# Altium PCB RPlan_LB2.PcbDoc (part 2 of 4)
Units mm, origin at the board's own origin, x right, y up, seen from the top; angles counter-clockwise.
Board outline 38.2 x 43.28 mm, 2 copper layers (Top Layer, Bottom Layer); 36 components, 100 nets, 269 pads, 31 vias.
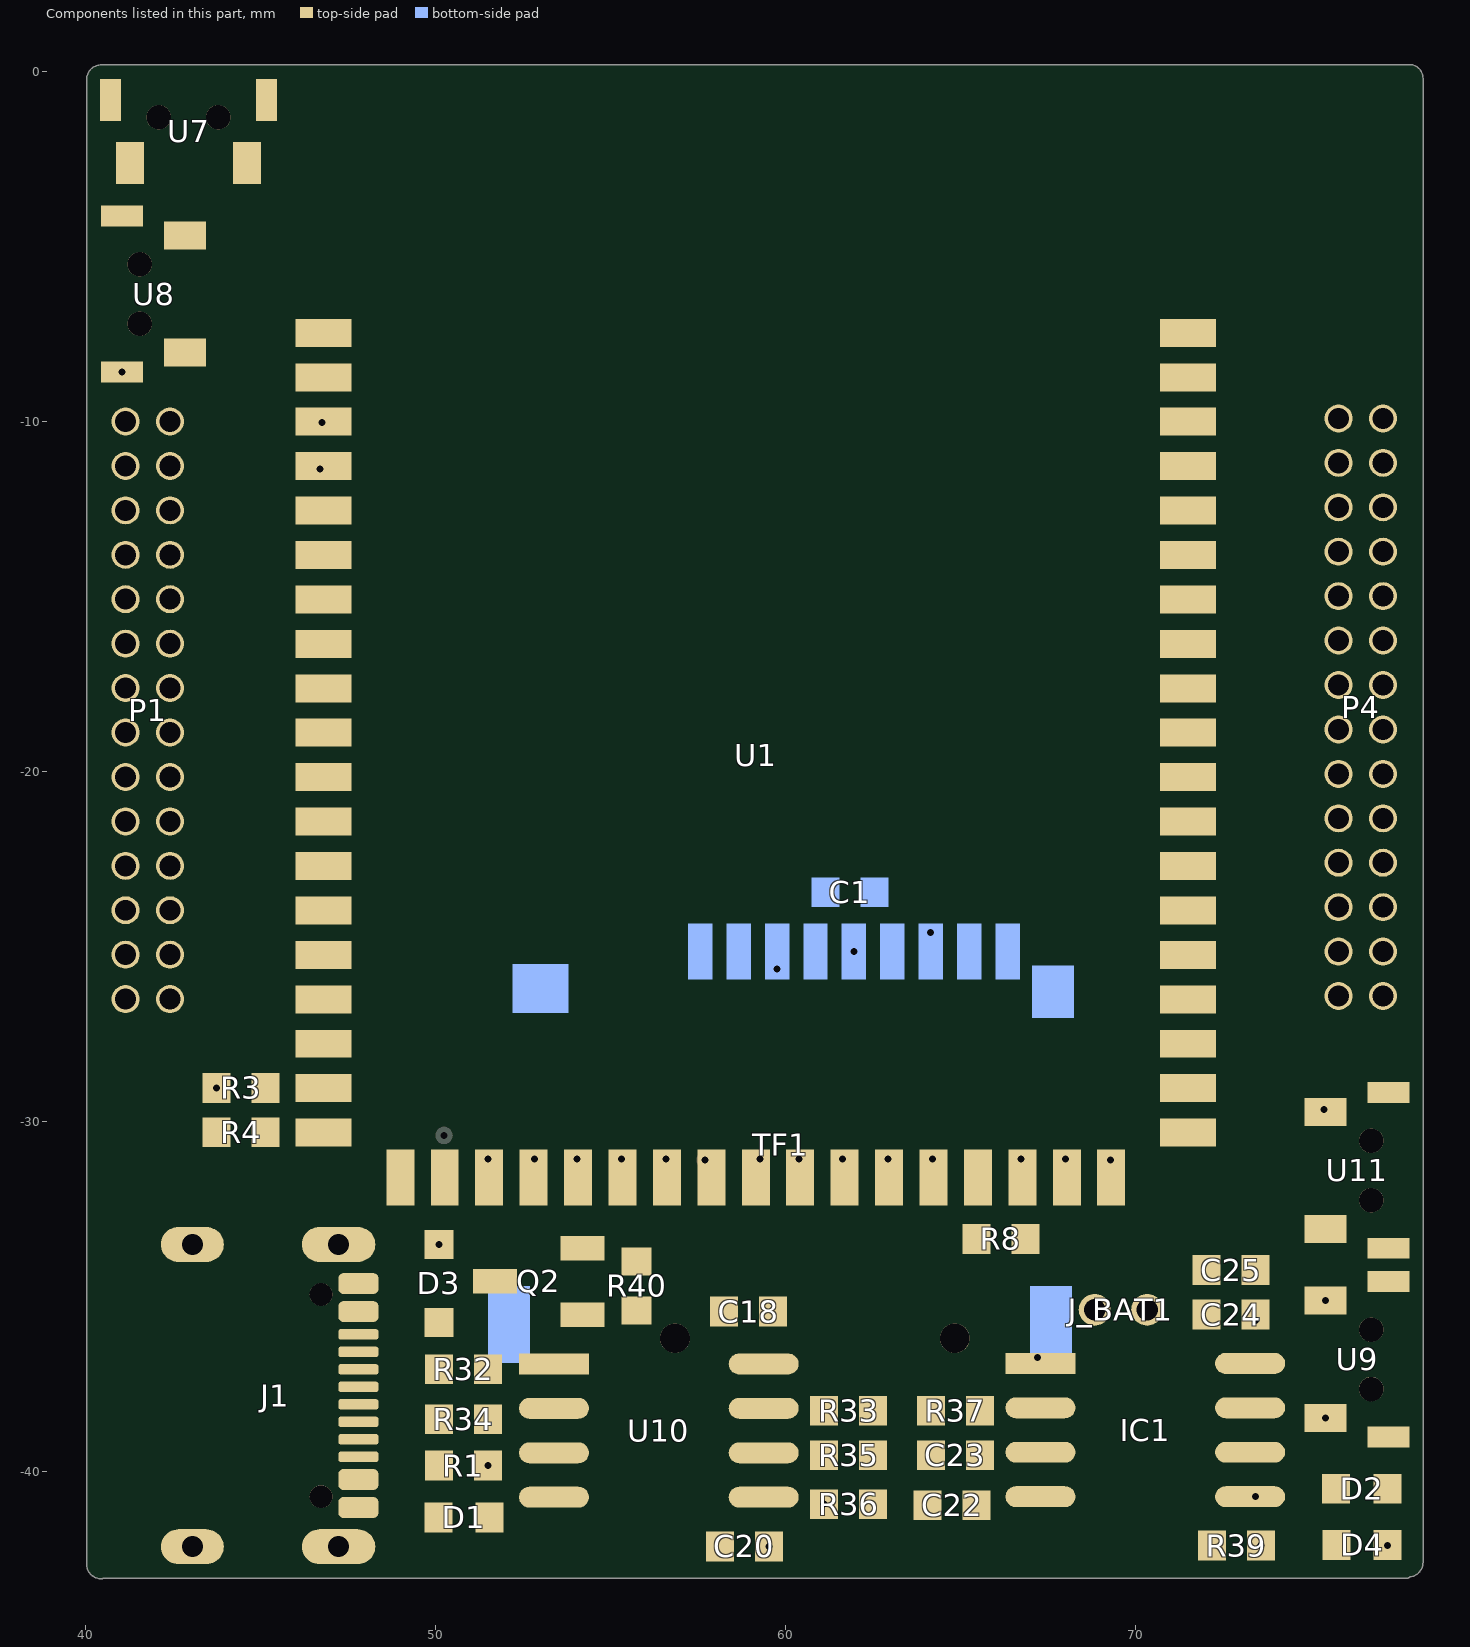
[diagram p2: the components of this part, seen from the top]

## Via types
v1: diameter 0.5, hole 0.3, Top Layer to Bottom Layer, 28 vias
v2: diameter 0.4, hole 0.2, Top Layer to Bottom Layer, 3 vias

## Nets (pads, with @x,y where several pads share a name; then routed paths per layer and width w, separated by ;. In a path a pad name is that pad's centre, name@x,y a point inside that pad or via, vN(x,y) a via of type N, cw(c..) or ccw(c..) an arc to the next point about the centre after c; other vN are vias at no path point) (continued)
copper on no net: (continued)
  Bottom Layer w0.025: 52.839,-22.09 53.525,-22.09 ; 52.839,-22.065 53.525,-22.065 ; 52.839,-22.04 53.525,-22.04 ; 52.839,-22.014 53.525,-22.014 ; 52.839,-21.989 53.525,-21.989 ; 52.839,-21.963 53.525,-21.963 ; 52.839,-21.938 53.525,-21.938 ; 52.839,-21.913 53.525,-21.913 ; 52.839,-21.887 53.525,-21.887 ; 52.839,-21.862 53.525,-21.862 ; 52.839,-21.836 53.525,-21.836 ; 52.839,-21.811 53.525,-21.811 ; 52.839,-21.786 53.525,-21.786 ; 52.839,-21.76 53.525,-21.76 ; 52.839,-21.43 53.525,-21.43 ; 52.839,-21.405 53.195,-21.405 ; 52.839,-21.379 53.195,-21.379 ; 52.839,-21.354 53.195,-21.354 ; 52.839,-21.328 53.195,-21.328 ; 52.839,-21.303 53.195,-21.303 ; 52.839,-21.278 53.195,-21.278 ; 52.839,-21.252 53.195,-21.252 ; 52.839,-21.227 53.195,-21.227 ; 52.839,-21.201 53.195,-21.201 ; 52.839,-21.176 53.195,-21.176 ; 52.839,-21.151 53.195,-21.151 ; 52.839,-21.125 53.195,-21.125 ; 52.839,-21.1 53.881,-21.1 ; 52.839,-21.074 53.881,-21.074 ; 52.839,-21.049 53.881,-21.049 ; 52.839,-21.024 53.881,-21.024 ; 52.839,-20.998 53.881,-20.998 ; 52.839,-20.973 53.881,-20.973 ; 52.839,-20.947 53.881,-20.947 ; 52.839,-20.922 53.881,-20.922 ; 52.839,-20.897 53.881,-20.897 ; 52.839,-20.871 53.881,-20.871 ; 52.839,-20.846 53.881,-20.846 ; 52.839,-20.82 53.881,-20.82 ; 52.839,-20.795 53.881,-20.795 ; 52.839,-20.77 53.881,-20.77 ; 52.839,-20.109 53.881,-20.109 ; 52.839,-20.084 53.881,-20.084 ; 52.839,-20.058 53.881,-20.058 ; 52.839,-20.033 53.881,-20.033 ; 52.839,-20.008 53.881,-20.008 ; 52.839,-19.982 53.881,-19.982 ; 52.839,-19.957 53.881,-19.957 ; 52.839,-19.931 53.881,-19.931 ; 52.839,-19.906 53.881,-19.906 ; 52.839,-19.881 53.881,-19.881 ; 52.839,-19.855 53.881,-19.855 ; 52.839,-19.83 53.881,-19.83 ; 52.839,-19.804 53.881,-19.804 ; 52.839,-19.779 53.881,-19.779 ; 52.839,-19.754 53.83,-19.754 ; 52.839,-19.728 53.195,-19.728 ; 52.839,-19.703 53.195,-19.703 ; 52.839,-19.677 53.195,-19.677 ; 52.839,-19.652 53.195,-19.652 ; 52.839,-19.627 53.195,-19.627 ; 52.839,-19.601 53.195,-19.601 ; 52.839,-19.576 53.195,-19.576 ; 52.839,-19.55 53.195,-19.55 ; 52.839,-19.525 53.195,-19.525 ; 52.839,-19.5 53.195,-19.5 ; 52.839,-19.474 53.195,-19.474 ; 52.839,-19.449 53.5,-19.449 ; 52.839,-19.119 53.525,-19.119 ; 52.839,-19.093 53.525,-19.093 ; 52.839,-19.068 53.195,-19.068 ; 52.839,-19.042 53.195,-19.042 ; 52.839,-19.017 53.195,-19.017 ; 52.839,-18.992 53.195,-18.992 ; 52.839,-18.966 53.195,-18.966 ; 52.839,-18.941 53.195,-18.941 ; 52.839,-18.915 53.195,-18.915 ; 52.839,-18.89 53.195,-18.89 ; 52.839,-18.865 53.195,-18.865 ; 52.839,-18.839 53.195,-18.839 ; 52.839,-18.814 53.195,-18.814 ; 52.839,-18.788 53.195,-18.788 ; 52.839,-18.763 53.525,-18.763 ; 52.839,-18.738 53.525,-18.738 ; 52.839,-18.712 53.525,-18.712 ; 52.839,-18.687 53.525,-18.687 ; 52.839,-18.661 53.525,-18.661 ; 52.839,-18.636 53.525,-18.636 ; 52.839,-18.611 53.525,-18.611 ; 52.839,-18.585 53.525,-18.585 ; 52.839,-18.56 53.525,-18.56 ; 52.839,-18.534 53.525,-18.534 ; 52.839,-18.509 53.525,-18.509 ; 52.839,-18.484 53.525,-18.484 ; 52.839,-18.458 53.525,-18.458 ; 52.839,-18.433 54.185,-18.433 ; 52.839,-18.407 54.185,-18.407 ; 52.839,-18.382 53.195,-18.382 ; 52.839,-18.357 53.195,-18.357 ; 52.839,-18.331 53.195,-18.331 ; 52.839,-18.306 53.195,-18.306 ; 52.839,-18.28 53.195,-18.28 ; 52.839,-18.255 53.195,-18.255 ; 52.839,-18.23 53.195,-18.23 ; 52.839,-18.204 53.195,-18.204 ; 52.839,-18.179 53.195,-18.179 ; 52.839,-18.153 53.195,-18.153 ; 52.839,-18.128 53.195,-18.128 ; 52.839,-18.103 53.195,-18.103 ; 52.839,-17.772 53.881,-17.772 ; 52.839,-17.747 53.525,-17.747 ; 52.839,-17.722 53.525,-17.722 ; 52.839,-17.696 53.525,-17.696 ; 52.839,-17.671 53.525,-17.671 ; 52.839,-17.645 53.525,-17.645 ; 52.839,-17.62 53.525,-17.62 ; 52.839,-17.595 53.525,-17.595 ; 52.839,-17.569 53.525,-17.569 ; 52.839,-17.544 53.525,-17.544 ; 52.839,-17.518 53.525,-17.518 ; 52.839,-17.493 53.525,-17.493 ; 52.839,-17.468 53.525,-17.468 ; 52.839,-17.442 53.525,-17.442 ; 52.839,-17.417 53.525,-17.417 ; 52.839,-17.391 53.195,-17.391 ; 52.839,-17.366 53.195,-17.366 ; 52.839,-17.341 53.195,-17.341 ; 52.839,-17.315 53.195,-17.315 ; 52.839,-17.29 53.195,-17.29 ; 52.839,-17.264 53.195,-17.264 ; 52.839,-17.239 53.195,-17.239 ; 52.839,-17.214 53.195,-17.214 ; 52.839,-17.188 53.195,-17.188 ; 52.839,-17.163 53.195,-17.163 ; 52.839,-17.137 53.195,-17.137 ; 52.839,-17.112 53.195,-17.112 ; 52.839,-17.087 53.195,-17.087 ; 52.839,-17.061 53.195,-17.061 ; 52.839,-17.036 53.195,-17.036 ; 52.839,-17.01 53.195,-17.01 ; 52.839,-16.985 53.195,-16.985 ; 52.839,-16.96 53.195,-16.96 ; 52.839,-16.934 53.195,-16.934 ; 52.839,-16.909 53.195,-16.909 ; 52.839,-16.883 53.195,-16.883 ; 52.839,-16.858 53.195,-16.858 ; 52.839,-16.833 53.195,-16.833 ; 52.839,-16.807 53.195,-16.807 ; 52.839,-16.782 53.195,-16.782 ; 52.839,-16.452 53.195,-16.452 ; 52.839,-16.426 53.195,-16.426 ; 52.839,-16.401 53.195,-16.401 ; 52.839,-16.375 53.195,-16.375 ; 52.839,-16.35 53.195,-16.35 ; 52.839,-16.325 53.195,-16.325 ; 52.839,-16.299 53.195,-16.299 ; 52.839,-16.274 53.195,-16.274 ; 52.839,-16.248 53.195,-16.248 ; 52.839,-16.223 53.195,-16.223 ; 52.839,-16.198 53.195,-16.198 ; 52.839,-16.172 53.195,-16.172 ; 52.839,-16.147 53.22,-16.147 ; 52.839,-16.121 53.22,-16.121 ; 52.839,-16.096 54.185,-16.096 ; 52.839,-16.071 54.185,-16.071 ; 52.839,-16.045 54.185,-16.045 ; 52.839,-16.02 54.185,-16.02 ; 52.839,-15.994 54.185,-15.994 ; 52.839,-15.969 54.185,-15.969 ; 52.839,-15.944 54.185,-15.944 ; 52.839,-15.918 54.185,-15.918 ; 52.839,-15.893 54.185,-15.893 ; 52.839,-15.867 54.185,-15.867 ; 52.839,-15.842 54.185,-15.842 ; 52.839,-15.817 54.185,-15.817 ; 52.839,-15.791 54.185,-15.791 ; 52.839,-15.766 54.185,-15.766 ; 52.839,-15.74 54.185,-15.74 ; 52.839,-15.715 54.185,-15.715 ; 52.839,-15.69 54.185,-15.69 ; 52.839,-15.664 54.185,-15.664 ; 52.839,-15.639 54.185,-15.639 ; 52.839,-15.613 54.185,-15.613 ; 52.839,-15.588 54.185,-15.588 ; 52.839,-15.563 54.185,-15.563 ; 52.839,-15.537 54.185,-15.537 ; 52.839,-15.512 54.185,-15.512 ; 52.839,-15.486 54.185,-15.486 ; 52.839,-15.461 54.185,-15.461 ; 52.839,-15.436 54.185,-15.436 ; 52.839,-14.775 53.881,-14.775 ; 52.839,-14.75 53.881,-14.75 ; 52.839,-14.724 53.881,-14.724 ; 52.839,-14.699 53.881,-14.699 ; 52.839,-14.674 53.881,-14.674 ; 52.839,-14.648 53.881,-14.648 ; 52.839,-14.623 53.881,-14.623 ; 52.839,-14.597 53.881,-14.597 ; 52.839,-14.572 53.881,-14.572 ; 52.839,-14.547 53.881,-14.547 ; 52.839,-14.521 53.881,-14.521 ; 52.839,-14.496 53.881,-14.496 ; 52.839,-14.47 54.185,-14.47 ; 52.839,-14.445 54.185,-14.445 ; 52.839,-14.42 54.185,-14.42 ; 52.839,-14.394 54.185,-14.394 ; 52.839,-14.369 54.185,-14.369 ; 52.839,-14.343 54.185,-14.343 ; 52.839,-14.318 54.185,-14.318 ; 52.839,-14.293 54.185,-14.293 ; 52.839,-14.267 54.185,-14.267 ; 52.839,-14.242 54.185,-14.242 ; 52.839,-14.216 54.185,-14.216 ; 52.839,-14.191 54.185,-14.191 ; 52.839,-14.166 54.185,-14.166 ; 52.839,-14.14 54.185,-14.14 ; 52.839,-14.115 54.185,-14.115 ; 52.839,-14.089 53.195,-14.089 ; 52.839,-14.064 53.195,-14.064 ; 52.839,-14.039 53.195,-14.039 ; 52.839,-14.013 53.195,-14.013 ; 52.839,-13.988 53.195,-13.988 ; 52.839,-13.962 53.195,-13.962 ; 52.839,-13.937 53.195,-13.937 ; 52.839,-13.912 53.195,-13.912 ; 52.839,-13.886 53.195,-13.886 ; 52.839,-13.861 53.195,-13.861 ; 52.839,-13.835 53.195,-13.835 ; 52.839,-13.81 53.195,-13.81 ; 52.839,-13.785 54.185,-13.785 ; 52.839,-13.759 54.185,-13.759 ; 52.839,-13.734 53.525,-13.734 ; 52.839,-13.708 53.525,-13.708 ; 52.839,-13.683 53.525,-13.683 ; 52.839,-13.658 53.525,-13.658 ; 52.839,-13.632 53.525,-13.632 ; 52.839,-13.607 53.525,-13.607 ; 52.839,-13.581 53.525,-13.581 ; 52.839,-13.556 53.525,-13.556 ; 52.839,-13.531 53.525,-13.531 ; 52.839,-13.505 53.525,-13.505 ; 52.839,-13.48 53.525,-13.48 ; 52.839,-13.454 53.525,-13.454 ; 52.839,-13.429 53.22,-13.429 ; 52.839,-13.404 53.195,-13.404 ; 52.839,-13.378 53.195,-13.378 ; 52.839,-13.353 53.195,-13.353 ; 52.839,-13.327 53.195,-13.327 ; 52.839,-13.302 53.195,-13.302 ; 52.839,-13.277 53.195,-13.277 ; 52.839,-13.251 53.195,-13.251 ; 52.839,-13.226 53.195,-13.226 ; 52.839,-13.2 53.195,-13.2 ; 52.839,-13.175 53.195,-13.175 ; 52.839,-13.15 53.195,-13.15 ; 52.839,-13.124 53.525,-13.124 ; 52.839,-13.099 53.525,-13.099 ; 52.839,-13.073 53.525,-13.073 ; 52.839,-13.048 53.525,-13.048 ; 52.839,-13.023 53.525,-13.023 ; 52.839,-12.997 53.525,-12.997 ; 52.839,-12.972 53.525,-12.972 ; 52.839,-12.946 53.525,-12.946 ; 52.839,-12.921 53.525,-12.921 ; 52.839,-12.896 53.525,-12.896 ; 52.839,-12.87 53.525,-12.87 ; 52.839,-12.845 53.525,-12.845 ; 52.839,-12.819 53.525,-12.819 ; 52.839,-12.794 53.525,-12.794 ; 52.839,-12.769 53.525,-12.769 ; 52.839,-12.743 53.195,-12.743 ; 52.839,-12.718 53.195,-12.718 ; 52.839,-12.692 53.195,-12.692 ; 52.839,-12.667 53.195,-12.667 ; 52.839,-12.642 53.195,-12.642 ; 52.839,-12.616 53.195,-12.616 ; 52.839,-12.591 53.195,-12.591 ; 52.839,-12.565 53.195,-12.565 ; 52.839,-12.54 53.195,-12.54 ; 52.839,-12.515 53.195,-12.515 ; 52.839,-12.489 53.195,-12.489 ; 52.839,-12.464 53.195,-12.464 ; 52.839,-12.438 53.195,-12.438 ; 52.839,-12.134 55.176,-12.134 ; 52.839,-12.108 55.201,-12.108 ; 52.839,-12.083 55.201,-12.083 ; 52.839,-12.057 55.201,-12.057 ; 52.839,-12.032 55.201,-12.032 ; 52.839,-12.007 55.201,-12.007 ; 52.839,-11.981 55.201,-11.981 ; 52.839,-11.956 55.201,-11.956 ; 52.839,-11.93 55.201,-11.93 ; 52.839,-11.905 55.201,-11.905 ; 52.839,-11.88 55.201,-11.88 ; 52.839,-11.854 55.201,-11.854 ; 52.839,-11.829 55.201,-11.829 ; 52.839,-11.803 55.201,-11.803 ; 52.839,-11.778 55.201,-11.778 ; 52.839,-11.753 53.195,-11.753 ; 52.839,-11.727 53.195,-11.727 ; 52.839,-11.702 53.195,-11.702 ; 52.839,-11.676 53.195,-11.676 ; 52.839,-11.651 53.195,-11.651 ; 52.839,-11.626 53.195,-11.626 ; 52.839,-11.6 53.195,-11.6 ; 52.839,-11.575 53.195,-11.575 ; 52.839,-11.549 53.195,-11.549 ; 52.839,-11.524 53.195,-11.524 ; 52.839,-11.499 53.195,-11.499 ; 52.839,-11.473 53.195,-11.473 ; 52.839,-11.448 53.195,-11.448 ; 52.839,-11.422 53.195,-11.422 ; 52.839,-11.397 53.195,-11.397 ; 52.839,-11.372 53.195,-11.372 ; 52.839,-11.346 53.195,-11.346 ; 52.839,-11.321 53.195,-11.321 ; 52.839,-11.295 53.195,-11.295 ; 52.839,-11.27 53.195,-11.27 ; 52.839,-11.245 53.195,-11.245 ; 52.839,-11.219 53.195,-11.219 ; 52.839,-11.194 53.195,-11.194 ; 52.839,-11.168 53.195,-11.168 ; 52.839,-11.143 53.195,-11.143 ; 52.839,-11.118 53.195,-11.118 ; 52.839,-11.092 53.195,-11.092 ; 52.839,-11.067 53.195,-11.067 ; 52.839,-11.041 53.195,-11.041 ; 52.839,-11.016 53.195,-11.016 ; 52.839,-10.991 53.195,-10.991 ; 52.839,-10.965 53.195,-10.965 ; 52.839,-10.94 53.195,-10.94 ; 52.839,-10.914 53.195,-10.914 ; 52.839,-10.889 53.195,-10.889 ; 52.839,-10.864 53.195,-10.864 ; 52.839,-10.838 53.195,-10.838 ; 52.839,-10.813 53.195,-10.813 ; 52.839,-10.787 53.195,-10.787 ; 52.839,-10.762 53.195,-10.762 ; 52.839,-10.737 53.195,-10.737 ; 52.839,-10.711 53.195,-10.711 ; 52.839,-10.686 53.195,-10.686 ; 52.839,-10.66 53.195,-10.66 ; 52.839,-10.635 53.195,-10.635 ; 52.839,-10.61 53.195,-10.61 ; 52.839,-10.584 53.195,-10.584 ; 52.839,-10.559 53.195,-10.559 ; 52.839,-10.533 53.195,-10.533 ; 52.839,-10.508 53.195,-10.508 ; 52.839,-10.483 53.195,-10.483 ; 52.839,-10.457 53.195,-10.457 ; 52.839,-10.432 53.195,-10.432 ; 52.839,-10.406 53.195,-10.406 ; 52.839,-10.381 53.195,-10.381 ; 52.839,-10.356 53.195,-10.356 ; 52.839,-10.33 53.195,-10.33 ; 52.839,-10.305 53.195,-10.305 ; 52.839,-10.279 53.195,-10.279 ; 52.839,-10.254 53.195,-10.254 ; 52.839,-10.229 53.195,-10.229 ; 52.839,-10.203 53.195,-10.203 ; 52.839,-10.178 53.195,-10.178 ; 52.839,-10.152 53.22,-10.152 ; 52.839,-10.127 55.201,-10.127 ; 52.839,-10.102 55.201,-10.102 ; 52.839,-10.076 55.201,-10.076 ; 52.839,-10.051 55.201,-10.051 ; 52.839,-10.025 55.201,-10.025 ; 52.839,-10 55.201,-10 ; 52.839,-9.975 55.201,-9.975 ; 52.839,-9.949 55.201,-9.949 ; 52.839,-9.924 55.201,-9.924 ; 52.839,-9.898 55.201,-9.898 ; 52.839,-9.873 55.201,-9.873 ; 52.839,-9.848 55.201,-9.848 ; 52.839,-9.822 55.201,-9.822 ; 52.839,-9.797 55.201,-9.797 ; 53.144,-21.735 53.525,-21.735 ; 53.144,-21.709 53.525,-21.709 ; 53.144,-21.684 53.525,-21.684 ; 53.144,-21.659 53.525,-21.659 ; 53.144,-21.633 53.525,-21.633 ; 53.144,-21.608 53.525,-21.608 ; 53.144,-21.582 53.525,-21.582 ; 53.144,-21.557 53.525,-21.557 ; 53.144,-21.532 53.525,-21.532 ; 53.144,-21.506 53.525,-21.506 ; 53.144,-21.481 53.525,-21.481 ; 53.144,-21.455 53.525,-21.455 ; 53.144,-19.423 53.525,-19.423 ; 53.144,-19.398 53.525,-19.398 ; 53.144,-19.373 53.525,-19.373 ; 53.144,-19.347 53.525,-19.347 ; 53.144,-19.322 53.525,-19.322 ; 53.144,-19.296 53.525,-19.296 ; 53.144,-19.271 53.525,-19.271 ; 53.144,-19.246 53.525,-19.246 ; 53.144,-19.22 53.525,-19.22 ; 53.144,-19.195 53.525,-19.195 ; 53.144,-19.169 53.525,-19.169 ; 53.144,-19.144 53.525,-19.144 ; 53.144,-15.105 53.525,-15.105 ; 53.144,-15.08 53.525,-15.08 ; 53.144,-15.055 53.525,-15.055 ; 53.144,-15.029 53.525,-15.029 ; 53.144,-15.004 53.525,-15.004 ; 53.144,-14.978 53.525,-14.978 ; 53.144,-14.953 53.525,-14.953 ; 53.144,-14.928 53.525,-14.928 ; 53.144,-14.902 53.525,-14.902 ; 53.144,-14.877 53.525,-14.877 ; 53.144,-14.851 53.525,-14.851 ; 53.144,-14.826 53.525,-14.826 ; 53.144,-14.801 53.525,-14.801 ; 53.5,-18.382 54.185,-18.382 ; 53.5,-18.357 54.185,-18.357 ; 53.5,-18.331 54.185,-18.331 ; 53.5,-18.306 54.185,-18.306 ; 53.5,-18.28 54.185,-18.28 ; 53.5,-18.255 54.185,-18.255 ; 53.5,-18.23 54.185,-18.23 ; 53.5,-18.204 54.185,-18.204 ; 53.5,-18.179 54.185,-18.179 ; 53.5,-18.153 54.185,-18.153 ; 53.5,-18.128 55.506,-18.128 ; 53.5,-18.103 55.506,-18.103 ; 53.5,-18.077 53.881,-18.077 ; 53.5,-18.052 53.881,-18.052 ; 53.5,-18.026 53.881,-18.026 ; 53.5,-18.001 53.881,-18.001 ; 53.5,-17.976 53.881,-17.976 ; 53.5,-17.95 53.881,-17.95 ; 53.5,-17.925 53.881,-17.925 ; 53.5,-17.899 53.881,-17.899 ; 53.5,-17.874 53.881,-17.874 ; 53.5,-17.849 53.881,-17.849 ; 53.5,-17.823 53.881,-17.823 ; 53.5,-17.798 53.881,-17.798 ; 53.5,-17.087 53.881,-17.087 ; 53.5,-17.061 53.881,-17.061 ; 53.5,-17.036 53.881,-17.036 ; 53.5,-17.01 53.881,-17.01 ; 53.5,-16.985 53.881,-16.985 ; 53.5,-16.96 53.881,-16.96 ; 53.5,-16.934 53.881,-16.934 ; 53.5,-16.909 53.881,-16.909 ; 53.5,-16.883 53.881,-16.883 ; 53.5,-16.858 53.881,-16.858 ; 53.5,-16.833 53.881,-16.833 ; 53.5,-16.807 53.881,-16.807 ; 53.5,-16.782 53.881,-16.782 ; 53.5,-14.089 54.185,-14.089 ; 53.5,-14.064 54.185,-14.064 ; 53.5,-14.039 54.185,-14.039 ; 53.5,-14.013 54.185,-14.013 ; 53.5,-13.988 54.185,-13.988 ; 53.5,-13.962 54.185,-13.962 ; 53.5,-13.937 54.185,-13.937 ; 53.5,-13.912 54.185,-13.912 ; 53.5,-13.886 54.185,-13.886 ; 53.5,-13.861 54.185,-13.861 ; 53.5,-13.835 54.185,-13.835 ; 53.5,-13.81 54.185,-13.81 ; 53.5,-11.448 54.516,-11.448 ; 53.5,-11.422 54.516,-11.422 ; 53.5,-11.397 54.516,-11.397 ; 53.5,-11.372 54.516,-11.372 ; 53.5,-11.346 54.516,-11.346 ; 53.5,-11.321 54.516,-11.321 ; 53.5,-11.295 54.516,-11.295 ; 53.5,-11.27 54.516,-11.27 ; 53.5,-11.245 54.516,-11.245 ; 53.5,-11.219 54.516,-11.219 ; 53.5,-11.194 54.516,-11.194 ; 53.5,-11.168 54.516,-11.168 ; 53.5,-11.143 54.516,-11.143 ; 53.5,-11.118 54.516,-11.118 ; 53.5,-11.092 54.516,-11.092 ; 53.5,-11.067 54.516,-11.067 ; 53.5,-11.041 54.516,-11.041 ; 53.5,-11.016 54.516,-11.016 ; 53.5,-10.991 54.516,-10.991 ; 53.5,-10.965 54.516,-10.965 ; 53.5,-10.94 54.516,-10.94 ; 53.5,-10.914 54.516,-10.914 ; 53.5,-10.889 54.516,-10.889 ; 53.5,-10.864 54.516,-10.864 ; 53.5,-10.838 54.516,-10.838 ; 53.5,-10.813 54.516,-10.813 ; 53.5,-10.787 54.516,-10.787 ; 53.5,-10.762 54.516,-10.762 ; 53.5,-10.737 54.516,-10.737 ; 53.5,-10.711 54.516,-10.711 ; 53.5,-10.686 54.516,-10.686 ; 53.5,-10.66 54.516,-10.66 ; 53.5,-10.635 54.516,-10.635 ; 53.5,-10.61 54.516,-10.61 ; 53.5,-10.584 54.516,-10.584 ; 53.5,-10.559 54.516,-10.559 ; 53.5,-10.533 54.516,-10.533 ; 53.5,-10.508 54.516,-10.508 ; 53.5,-10.483 54.516,-10.483 ; 53.5,-10.457 54.516,-10.457 ; 53.83,-21.786 54.185,-21.786 ; 53.83,-21.76 54.185,-21.76 ; 53.83,-21.735 54.185,-21.735 ; 53.83,-21.709 54.185,-21.709 ; 53.83,-21.684 54.185,-21.684 ; 53.83,-21.659 54.185,-21.659 ; 53.83,-21.633 54.185,-21.633 ; 53.83,-21.608 54.185,-21.608 ; 53.83,-21.582 54.185,-21.582 ; 53.83,-21.557 54.185,-21.557 ; 53.83,-21.532 54.185,-21.532 ; 53.83,-21.506 54.185,-21.506 ; 53.83,-21.481 54.185,-21.481 ; 53.83,-21.455 54.185,-21.455 ; 53.83,-21.43 54.871,-21.43 ; 53.83,-20.744 55.862,-20.744 ; 53.83,-20.719 55.862,-20.719 ; 53.83,-20.693 55.862,-20.693 ; 53.83,-20.668 55.862,-20.668 ; 53.83,-20.643 55.862,-20.643 ; 53.83,-20.617 55.862,-20.617 ; 53.83,-20.592 55.862,-20.592 ; 53.83,-20.566 55.862,-20.566 ; 53.83,-20.541 55.862,-20.541 ; 53.83,-20.516 55.862,-20.516 ; 53.83,-20.49 55.862,-20.49 ; 53.83,-20.465 55.862,-20.465 ; 53.83,-20.439 57.487,-20.439 ; 53.83,-19.449 56.167,-19.449 ; 53.83,-19.423 56.192,-19.423 ; 53.83,-19.398 56.192,-19.398 ; 53.83,-19.373 56.192,-19.373 ; 53.83,-19.347 56.192,-19.347 ; 53.83,-19.322 56.192,-19.322 ; 53.83,-19.296 56.192,-19.296 ; 53.83,-19.271 56.192,-19.271 ; 53.83,-19.246 56.192,-19.246 ; 53.83,-19.22 56.192,-19.22 ; 53.83,-19.195 56.192,-19.195 ; 53.83,-19.169 56.192,-19.169 ; 53.83,-19.144 56.192,-19.144 ; 53.83,-19.119 57.538,-19.119 ; 53.83,-19.093 57.538,-19.093 ; 53.83,-17.442 54.516,-17.442 ; 53.83,-17.417 54.516,-17.417 ; 53.83,-17.391 54.516,-17.391 ; 53.83,-17.366 54.516,-17.366 ; 53.83,-17.341 54.516,-17.341 ; 53.83,-17.315 54.516,-17.315 ; 53.83,-17.29 54.516,-17.29 ; 53.83,-17.264 54.516,-17.264 ; 53.83,-17.239 54.516,-17.239 ; 53.83,-17.214 54.516,-17.214 ; 53.83,-17.188 54.516,-17.188 ; 53.83,-17.163 54.516,-17.163 ; 53.83,-17.137 54.516,-17.137 ; 53.83,-17.112 54.516,-17.112 ; 53.83,-15.41 54.185,-15.41 ; 53.83,-15.385 54.185,-15.385 ; 53.83,-15.359 54.185,-15.359 ; 53.83,-15.334 54.185,-15.334 ; 53.83,-15.309 54.185,-15.309 ; 53.83,-15.283 54.185,-15.283 ; 53.83,-15.258 54.185,-15.258 ; 53.83,-15.232 54.185,-15.232 ; 53.83,-15.207 54.185,-15.207 ; 53.83,-15.182 54.185,-15.182 ; 53.83,-15.156 54.185,-15.156 ; 53.83,-15.131 54.185,-15.131 ; 53.83,-15.105 54.185,-15.105 ; 53.83,-13.48 54.185,-13.48 ; 53.83,-13.454 54.185,-13.454 ; 53.83,-13.429 54.185,-13.429 ; 53.83,-13.404 54.185,-13.404 ; 53.83,-13.378 54.185,-13.378 ; 53.83,-13.353 54.185,-13.353 ; 53.83,-13.327 54.185,-13.327 ; 53.83,-13.302 54.185,-13.302 ; 53.83,-13.277 54.185,-13.277 ; 53.83,-13.251 54.185,-13.251 ; 53.83,-13.226 54.185,-13.226 ; 53.83,-13.2 54.185,-13.2 ; 53.83,-13.175 54.185,-13.175 ; 53.83,-13.15 54.185,-13.15 ; 53.83,-13.124 54.185,-13.124 ; 53.83,-13.099 54.185,-13.099 ; 53.83,-13.073 54.185,-13.073 ; 53.83,-13.048 54.185,-13.048 ; 53.83,-13.023 54.185,-13.023 ; 53.83,-12.997 54.185,-12.997 ; 53.83,-12.972 54.185,-12.972 ; 53.83,-12.946 54.185,-12.946 ; 53.83,-12.921 54.185,-12.921 ; 53.83,-12.896 54.185,-12.896 ; 53.83,-12.87 54.185,-12.87 ; 53.83,-12.845 54.185,-12.845 ; 53.83,-12.819 54.185,-12.819 ; 53.83,-12.794 54.185,-12.794 ; 53.83,-12.769 54.185,-12.769 ; 53.83,-12.743 54.185,-12.743 ; 53.83,-12.718 54.185,-12.718 ; 53.83,-12.692 54.185,-12.692 ; 53.83,-12.667 54.185,-12.667 ; 53.83,-12.642 54.185,-12.642 ; 53.83,-12.616 54.185,-12.616 ; 53.83,-12.591 54.185,-12.591 ; 53.83,-12.565 54.185,-12.565 ; 53.83,-12.54 54.185,-12.54 ; 53.83,-12.515 54.185,-12.515 ; 53.83,-12.489 54.185,-12.489 ; 53.83,-12.464 54.185,-12.464 ; 53.83,-12.438 54.185,-12.438 ; 54.185,-21.405 54.871,-21.405 ; 54.185,-21.379 54.871,-21.379 ; 54.185,-21.354 54.871,-21.354 ; 54.185,-21.328 54.871,-21.328 ; 54.185,-21.303 54.871,-21.303 ; 54.185,-21.278 54.871,-21.278 ; 54.185,-21.252 54.871,-21.252 ; 54.185,-21.227 54.871,-21.227 ; 54.185,-21.201 54.871,-21.201 ; 54.185,-21.176 54.871,-21.176 ; 54.185,-21.151 54.871,-21.151 ; 54.185,-21.125 54.871,-21.125 ; 54.185,-21.1 54.871,-21.1 ; 54.185,-21.074 54.871,-21.074 ; 54.185,-20.414 54.516,-20.414 ; 54.185,-20.389 54.516,-20.389 ; 54.185,-20.363 54.516,-20.363 ; 54.185,-20.338 54.516,-20.338 ; 54.185,-20.312 54.516,-20.312 ; 54.185,-20.287 54.516,-20.287 ; 54.185,-20.262 54.516,-20.262 ; 54.185,-20.236 54.516,-20.236 ; 54.185,-20.211 54.516,-20.211 ; 54.185,-20.185 54.516,-20.185 ; 54.185,-20.16 54.516,-20.16 ; 54.185,-20.135 54.516,-20.135 ; 54.185,-20.109 54.516,-20.109 ; 54.185,-20.084 54.516,-20.084 ; 54.185,-20.058 54.516,-20.058 ; 54.185,-20.033 54.516,-20.033 ; 54.185,-20.008 54.516,-20.008 ; 54.185,-19.982 54.516,-19.982 ; 54.185,-19.957 54.516,-19.957 ; 54.185,-19.931 54.516,-19.931 ; 54.185,-19.906 54.516,-19.906 ; 54.185,-19.881 54.516,-19.881 ; 54.185,-19.855 54.516,-19.855 ; 54.185,-19.83 54.516,-19.83 ; 54.185,-19.804 54.516,-19.804 ; 54.185,-19.779 54.516,-19.779 ; 54.185,-19.754 54.516,-19.754 ; 54.185,-19.728 54.516,-19.728 ; 54.185,-19.703 54.516,-19.703 ; 54.185,-19.677 54.516,-19.677 ; 54.185,-19.652 54.516,-19.652 ; 54.185,-19.627 54.516,-19.627 ; 54.185,-19.601 54.516,-19.601 ; 54.185,-19.576 54.516,-19.576 ; 54.185,-19.55 54.516,-19.55 ; 54.185,-19.525 54.516,-19.525 ; 54.185,-19.5 54.516,-19.5 ; 54.185,-19.474 54.516,-19.474 ; 54.185,-18.077 55.506,-18.077 ; 54.185,-18.052 55.506,-18.052 ; 54.185,-18.026 55.506,-18.026 ; 54.185,-18.001 55.506,-18.001 ; 54.185,-17.976 55.506,-17.976 ; 54.185,-17.95 55.506,-17.95 ; 54.185,-17.925 55.506,-17.925 ; 54.185,-17.899 55.506,-17.899 ; 54.185,-17.874 55.506,-17.874 ; 54.185,-17.849 55.506,-17.849 ; 54.185,-17.823 55.506,-17.823 ; 54.185,-17.798 55.506,-17.798 ; 54.185,-17.772 58.173,-17.772 ; 54.185,-16.452 56.192,-16.452 ; 54.185,-16.426 56.192,-16.426 ; 54.185,-16.401 54.516,-16.401 ; 54.185,-16.375 54.516,-16.375 ; 54.185,-16.35 54.516,-16.35 ; 54.185,-16.325 54.516,-16.325 ; 54.185,-16.299 54.516,-16.299 ; 54.185,-16.274 54.516,-16.274 ; 54.185,-16.248 54.516,-16.248 ; 54.185,-16.223 54.516,-16.223 ; 54.185,-16.198 54.516,-16.198 ; 54.185,-16.172 54.516,-16.172 ; 54.185,-16.147 54.516,-16.147 ; 54.185,-16.121 54.516,-16.121 ; 54.49,-22.09 55.862,-22.09 ; 54.49,-22.065 55.862,-22.065 ; 54.49,-22.04 55.862,-22.04 ; 54.49,-22.014 55.862,-22.014 ; 54.49,-21.989 55.862,-21.989 ; 54.49,-21.963 55.862,-21.963 ; 54.49,-21.938 55.862,-21.938 ; 54.49,-21.913 55.862,-21.913 ; 54.49,-21.887 55.862,-21.887 ; 54.49,-21.862 55.862,-21.862 ; 54.49,-21.836 55.862,-21.836 ; 54.49,-21.811 55.862,-21.811 ; 54.49,-21.786 56.852,-21.786 ; 54.49,-21.76 56.852,-21.76 ; 54.49,-19.068 57.183,-19.068 ; 54.49,-19.042 57.183,-19.042 ; 54.49,-19.017 57.183,-19.017 ; 54.49,-18.992 57.183,-18.992 ; 54.49,-18.966 57.183,-18.966 ; 54.49,-18.941 57.183,-18.941 ; 54.49,-18.915 57.183,-18.915 ; 54.49,-18.89 57.183,-18.89 ; 54.49,-18.865 57.183,-18.865 ; 54.49,-18.839 57.183,-18.839 ; 54.49,-18.814 57.183,-18.814 ; 54.49,-18.788 57.183,-18.788 ; 54.49,-16.756 56.192,-16.756 ; 54.49,-16.731 56.192,-16.731 ; 54.49,-16.706 56.192,-16.706 ; 54.49,-16.68 56.192,-16.68 ; 54.49,-16.655 56.192,-16.655 ; 54.49,-16.629 56.192,-16.629 ; 54.49,-16.604 56.192,-16.604 ; 54.49,-16.579 56.192,-16.579 ; 54.49,-16.553 56.192,-16.553 ; 54.49,-16.528 56.192,-16.528 ; 54.49,-16.502 56.192,-16.502 ; 54.49,-16.477 56.192,-16.477 ; 54.49,-15.41 55.862,-15.41 ; 54.49,-15.385 55.862,-15.385 ; 54.49,-15.359 55.862,-15.359 ; 54.49,-15.334 55.862,-15.334 ; 54.49,-15.309 55.862,-15.309 ; 54.49,-15.283 55.862,-15.283 ; 54.49,-15.258 55.862,-15.258 ; 54.49,-15.232 55.862,-15.232 ; 54.49,-15.207 55.862,-15.207 ; 54.49,-15.182 55.862,-15.182 ; 54.49,-15.156 55.862,-15.156 ; 54.49,-15.131 55.862,-15.131 ; 54.49,-15.105 55.862,-15.105 ; 54.49,-15.08 54.871,-15.08 ; 54.49,-15.055 54.871,-15.055 ; 54.49,-15.029 54.871,-15.029 ; 54.49,-15.004 54.871,-15.004 ; 54.49,-14.978 54.871,-14.978 ; 54.49,-14.953 54.871,-14.953 ; 54.49,-14.928 54.871,-14.928 ; 54.49,-14.902 54.871,-14.902 ; 54.49,-14.877 54.871,-14.877 ; 54.49,-14.851 54.871,-14.851 ; 54.49,-14.826 54.871,-14.826 ; 54.49,-14.801 54.871,-14.801 ; 54.49,-14.775 55.201,-14.775 ; 54.49,-14.75 55.201,-14.75 ; 54.49,-14.724 55.201,-14.724 ; 54.49,-14.699 55.201,-14.699 ; 54.49,-14.674 55.201,-14.674 ; 54.49,-14.648 55.201,-14.648 ; 54.49,-14.623 55.201,-14.623 ; 54.49,-14.597 55.201,-14.597 ; 54.49,-14.572 55.201,-14.572 ; 54.49,-14.547 55.201,-14.547 ; 54.49,-14.521 55.201,-14.521 ; 54.49,-14.496 55.201,-14.496 ; 54.49,-14.47 55.201,-14.47 ; 54.49,-14.445 55.201,-14.445 ; 54.49,-14.42 55.201,-14.42 ; 54.49,-14.394 55.201,-14.394 ; 54.49,-14.369 55.201,-14.369 ; 54.49,-14.343 55.201,-14.343 ; 54.49,-14.318 55.201,-14.318 ; 54.49,-14.293 55.201,-14.293 ; 54.49,-14.267 55.201,-14.267 ; 54.49,-14.242 55.201,-14.242 ; 54.49,-14.216 55.201,-14.216 ; 54.49,-14.191 55.201,-14.191 ; 54.49,-14.166 55.201,-14.166 ; 54.49,-14.14 55.201,-14.14 ; 54.49,-14.115 55.201,-14.115 ; 54.49,-14.089 55.201,-14.089 ; 54.49,-14.064 55.201,-14.064 ; 54.49,-14.039 55.201,-14.039 ; 54.49,-14.013 55.201,-14.013 ; 54.49,-13.988 55.201,-13.988 ; 54.49,-13.962 55.201,-13.962 ; 54.49,-13.937 55.201,-13.937 ; 54.49,-13.912 55.201,-13.912 ; 54.49,-13.886 55.201,-13.886 ; 54.49,-13.861 55.201,-13.861 ; 54.49,-13.835 55.201,-13.835 ; 54.49,-13.81 55.201,-13.81 ; 54.49,-13.785 54.897,-13.785 ; 54.49,-13.759 54.897,-13.759 ; 54.49,-13.734 54.871,-13.734 ; 54.49,-13.708 54.871,-13.708 ; 54.49,-13.683 54.871,-13.683 ; 54.49,-13.658 54.871,-13.658 ; 54.49,-13.632 54.871,-13.632 ; 54.49,-13.607 54.871,-13.607 ; 54.49,-13.581 54.871,-13.581 ; 54.49,-13.556 54.871,-13.556 ; 54.49,-13.531 54.871,-13.531 ; 54.49,-13.505 54.871,-13.505 ; 54.49,-13.48 55.506,-13.48 ; 54.49,-13.454 55.506,-13.454 ; 54.49,-13.429 55.201,-13.429 ; 54.49,-13.404 55.201,-13.404 ; 54.49,-13.378 55.201,-13.378 ; 54.49,-13.353 55.201,-13.353 ; 54.49,-13.327 55.201,-13.327 ; 54.49,-13.302 55.201,-13.302 ; 54.49,-13.277 55.201,-13.277 ; 54.49,-13.251 55.201,-13.251 ; 54.49,-13.226 55.201,-13.226 ; 54.49,-13.2 55.201,-13.2 ; 54.49,-13.175 55.201,-13.175 ; 54.49,-13.15 55.201,-13.15 ; 54.49,-13.124 55.201,-13.124 ; 54.516,-18.763 57.843,-18.763 ; 54.516,-16.782 56.192,-16.782 ; 54.516,-15.461 55.862,-15.461 ; 54.516,-15.436 55.862,-15.436 ; 54.82,-20.109 55.201,-20.109 ; 54.82,-20.084 55.201,-20.084 ; 54.82,-20.058 55.201,-20.058 ; 54.82,-20.033 55.201,-20.033 ; 54.82,-20.008 55.201,-20.008 ; 54.82,-19.982 55.201,-19.982 ; 54.82,-19.957 55.201,-19.957 ; 54.82,-19.931 55.201,-19.931 ; 54.82,-19.906 55.201,-19.906 ; 54.82,-19.881 55.201,-19.881 ; 54.82,-19.855 55.201,-19.855 ; 54.82,-19.83 55.201,-19.83 ; 54.82,-19.804 55.201,-19.804 ; 54.82,-19.779 55.201,-19.779 ; 54.82,-19.754 55.176,-19.754 ; 54.82,-17.747 55.201,-17.747 ; 54.82,-17.722 55.201,-17.722 ; 54.82,-17.696 55.201,-17.696 ; 54.82,-17.671 55.201,-17.671 ; 54.82,-17.645 55.201,-17.645 ; 54.82,-17.62 55.201,-17.62 ; 54.82,-17.595 55.201,-17.595 ; 54.82,-17.569 55.201,-17.569 ; 54.82,-17.544 55.201,-17.544 ; 54.82,-17.518 55.201,-17.518 ; 54.82,-17.493 55.201,-17.493 ; 54.82,-17.468 55.201,-17.468 ; 54.82,-17.442 55.201,-17.442 ; 54.82,-17.417 55.201,-17.417 ; 54.82,-17.391 55.201,-17.391 ; 54.82,-17.366 55.201,-17.366 ; 54.82,-17.341 55.201,-17.341 ; 54.82,-17.315 55.201,-17.315 ; 54.82,-17.29 55.201,-17.29 ; 54.82,-17.264 55.201,-17.264 ; 54.82,-17.239 55.201,-17.239 ; 54.82,-17.214 55.201,-17.214 ; 54.82,-17.188 55.201,-17.188 ; 54.82,-17.163 55.201,-17.163 ; 54.82,-17.137 55.201,-17.137 ; 54.82,-17.112 55.201,-17.112 ; 54.82,-17.087 55.201,-17.087 ; 54.82,-17.061 55.201,-17.061 ; 54.82,-17.036 55.201,-17.036 ; 54.82,-17.01 55.201,-17.01 ; 54.82,-16.985 55.201,-16.985 ; 54.82,-16.96 55.201,-16.96 ; 54.82,-16.934 55.201,-16.934 ; 54.82,-16.909 55.201,-16.909 ; 54.82,-16.883 55.201,-16.883 ; 54.82,-16.858 55.201,-16.858 ; 54.82,-16.833 55.201,-16.833 ; 54.82,-16.807 55.201,-16.807 ; 54.82,-16.401 55.201,-16.401 ; 54.82,-16.375 55.201,-16.375 ; 54.82,-16.35 55.201,-16.35 ; 54.82,-16.325 55.201,-16.325 ; 54.82,-16.299 55.201,-16.299 ; 54.82,-16.274 55.201,-16.274 ; 54.82,-16.248 55.201,-16.248 ; 54.82,-16.223 55.201,-16.223 ; 54.82,-16.198 55.201,-16.198 ; 54.82,-16.172 55.201,-16.172 ; 54.82,-16.147 55.201,-16.147 ; 54.82,-16.121 55.201,-16.121 ; 54.82,-16.096 55.862,-16.096 ; 54.82,-16.071 55.862,-16.071 ; 54.82,-16.045 55.862,-16.045 ; 54.82,-16.02 55.862,-16.02 ; 54.82,-15.994 55.862,-15.994 ; 54.82,-15.969 55.862,-15.969 ; 54.82,-15.944 55.862,-15.944 ; 54.82,-15.918 55.862,-15.918 ; 54.82,-15.893 55.862,-15.893 ; 54.82,-15.867 55.862,-15.867 ; 54.82,-15.842 55.862,-15.842 ; 54.82,-15.817 55.862,-15.817 ; 54.82,-15.791 55.862,-15.791 ; 54.82,-15.766 55.201,-15.766 ; 54.82,-15.74 55.201,-15.74 ; 54.82,-15.715 55.201,-15.715 ; 54.82,-15.69 55.201,-15.69 ; 54.82,-15.664 55.201,-15.664 ; 54.82,-15.639 55.201,-15.639 ; 54.82,-15.613 55.201,-15.613 ; 54.82,-15.588 55.201,-15.588 ; 54.82,-15.563 55.201,-15.563 ; 54.82,-15.537 55.201,-15.537 ; 54.82,-15.512 55.201,-15.512 ; 54.82,-15.486 55.201,-15.486 ; 54.82,-11.753 55.201,-11.753 ; 54.82,-11.727 55.201,-11.727 ; 54.82,-11.702 55.201,-11.702 ; 54.82,-11.676 55.201,-11.676 ; 54.82,-11.651 55.201,-11.651 ; 54.82,-11.626 55.201,-11.626 ; 54.82,-11.6 55.201,-11.6 ; 54.82,-11.575 55.201,-11.575 ; 54.82,-11.549 55.201,-11.549 ; 54.82,-11.524 55.201,-11.524 ; 54.82,-11.499 55.201,-11.499 ; 54.82,-11.473 55.201,-11.473 ; 54.82,-11.448 55.201,-11.448 ; 54.82,-11.422 55.201,-11.422 ; 54.82,-11.397 55.201,-11.397 ; 54.82,-11.372 55.201,-11.372 ; 54.82,-11.346 55.201,-11.346 ; 54.82,-11.321 55.201,-11.321 ; 54.82,-11.295 55.201,-11.295 ; 54.82,-11.27 55.201,-11.27 ; 54.82,-11.245 55.201,-11.245 ; 54.82,-11.219 55.201,-11.219 ; 54.82,-11.194 55.201,-11.194 ; 54.82,-11.168 55.201,-11.168 ; 54.82,-11.143 55.201,-11.143 ; 54.82,-11.118 55.201,-11.118 ; 54.82,-11.092 55.201,-11.092 ; 54.82,-11.067 55.201,-11.067 ; 54.82,-11.041 55.201,-11.041 ; 54.82,-11.016 55.201,-11.016 ; 54.82,-10.991 55.201,-10.991 ; 54.82,-10.965 55.201,-10.965 ; 54.82,-10.94 55.201,-10.94 ; 54.82,-10.914 55.201,-10.914 ; 54.82,-10.889 55.201,-10.889 ; 54.82,-10.864 55.201,-10.864 ; 54.82,-10.838 55.201,-10.838 ; 54.82,-10.813 55.201,-10.813 ; 54.82,-10.787 55.201,-10.787 ; 54.82,-10.762 55.201,-10.762 ; 54.82,-10.737 55.201,-10.737 ; 54.82,-10.711 55.201,-10.711 ; 54.82,-10.686 55.201,-10.686 ; 54.82,-10.66 55.201,-10.66 ; 54.82,-10.635 55.201,-10.635 ; 54.82,-10.61 55.201,-10.61 ; 54.82,-10.584 55.201,-10.584 ; 54.82,-10.559 55.201,-10.559 ; 54.82,-10.533 55.201,-10.533 ; 54.82,-10.508 55.201,-10.508 ; 54.82,-10.483 55.201,-10.483 ; 54.82,-10.457 55.201,-10.457 ; 54.82,-10.432 55.201,-10.432 ; 54.82,-10.406 55.201,-10.406 ; 54.82,-10.381 55.201,-10.381 ; 54.82,-10.356 55.201,-10.356 ; 54.82,-10.33 55.201,-10.33 ; 54.82,-10.305 55.201,-10.305 ; 54.82,-10.279 55.201,-10.279 ; 54.82,-10.254 55.201,-10.254 ; 54.82,-10.229 55.201,-10.229 ; 54.82,-10.203 55.201,-10.203 ; 54.82,-10.178 55.201,-10.178 ; 54.82,-10.152 55.201,-10.152 ; 54.973,-13.785 55.049,-13.785 ; 54.973,-13.759 55.049,-13.759 ; 55.1,-13.785 55.125,-13.785 ; 55.1,-13.759 55.125,-13.759 ; 55.176,-21.735 56.852,-21.735 ; 55.176,-21.709 56.852,-21.709 ; 55.176,-21.684 56.852,-21.684 ; 55.176,-21.659 56.852,-21.659 ; 55.176,-21.633 56.852,-21.633 ; 55.176,-21.608 56.852,-21.608 ; 55.176,-21.582 56.852,-21.582 ; 55.176,-21.557 56.852,-21.557 ; 55.176,-21.532 56.852,-21.532 ; 55.176,-21.506 56.852,-21.506 ; 55.176,-21.481 56.852,-21.481 ; 55.176,-21.455 56.852,-21.455 ; 55.176,-21.43 57.183,-21.43 ; 55.176,-21.1 56.192,-21.1 ; 55.176,-21.074 56.192,-21.074 ; 55.176,-21.049 55.862,-21.049 ; 55.176,-21.024 55.862,-21.024 ; 55.176,-20.998 55.862,-20.998 ; 55.176,-20.973 55.862,-20.973 ; 55.176,-20.947 55.862,-20.947 ; 55.176,-20.922 55.862,-20.922 ; 55.176,-20.897 55.862,-20.897 ; 55.176,-20.871 55.862,-20.871 ; 55.176,-20.846 55.862,-20.846 ; 55.176,-20.82 55.862,-20.82 ; 55.176,-20.795 55.862,-20.795 ; 55.176,-20.77 55.862,-20.77 ; 55.176,-18.433 55.862,-18.433 ; 55.176,-18.407 55.862,-18.407 ; 55.176,-18.382 55.506,-18.382 ; 55.176,-18.357 55.506,-18.357 ; 55.176,-18.331 55.506,-18.331 ; 55.176,-18.306 55.506,-18.306 ; 55.176,-18.28 55.506,-18.28 ; 55.176,-18.255 55.506,-18.255 ; 55.176,-18.23 55.506,-18.23 ; 55.176,-18.204 55.506,-18.204 ; 55.176,-18.179 55.506,-18.179 ; 55.176,-18.153 55.506,-18.153 ; 55.176,-13.785 57.843,-13.785 ; 55.176,-13.759 57.843,-13.759 ; 55.176,-13.734 55.506,-13.734 ; 55.176,-13.708 55.506,-13.708 ; 55.176,-13.683 55.506,-13.683 ; 55.176,-13.658 55.506,-13.658 ; 55.176,-13.632 55.506,-13.632 ; 55.176,-13.607 55.506,-13.607 ; 55.176,-13.581 55.506,-13.581 ; 55.176,-13.556 55.506,-13.556 ; 55.176,-13.531 55.506,-13.531 ; 55.176,-13.505 55.506,-13.505 ; 55.176,-12.794 55.506,-12.794 ; 55.176,-12.769 55.506,-12.769 ; 55.176,-12.743 55.506,-12.743 ; 55.176,-12.718 55.506,-12.718 ; 55.176,-12.692 55.506,-12.692 ; 55.176,-12.667 55.506,-12.667 ; 55.176,-12.642 55.506,-12.642 ; 55.176,-12.616 55.506,-12.616 ; 55.176,-12.591 55.506,-12.591 ; 55.176,-12.565 55.506,-12.565 ; 55.176,-12.54 55.506,-12.54 ; 55.176,-12.515 55.506,-12.515 ; 55.176,-12.489 55.506,-12.489 ; 55.176,-12.464 55.506,-12.464 ; 55.176,-12.438 57.843,-12.438 ; 55.481,-21.405 56.192,-21.405 ; 55.481,-21.379 56.192,-21.379 ; 55.481,-21.354 56.192,-21.354 ; 55.481,-21.328 56.192,-21.328 ; 55.481,-21.303 56.192,-21.303 ; 55.481,-21.278 56.192,-21.278 ; 55.481,-21.252 56.192,-21.252 ; 55.481,-21.227 56.192,-21.227 ; 55.481,-21.201 56.192,-21.201 ; 55.481,-21.176 56.192,-21.176 ; 55.481,-21.151 56.192,-21.151 ; 55.481,-21.125 56.192,-21.125 ; 55.481,-20.414 56.852,-20.414 ; 55.481,-20.389 56.852,-20.389 ; 55.481,-20.363 56.852,-20.363 ; 55.481,-20.338 56.852,-20.338 ; 55.481,-20.312 56.852,-20.312 ; 55.481,-20.287 56.852,-20.287 ; 55.481,-20.262 56.852,-20.262 ; 55.481,-20.236 56.852,-20.236 ; 55.481,-20.211 56.852,-20.211 ; 55.481,-20.185 56.852,-20.185 ; 55.481,-20.16 56.852,-20.16 ; 55.481,-20.135 56.852,-20.135 ; 55.481,-20.109 57.538,-20.109 ; 55.481,-20.084 57.538,-20.084 ; 55.481,-20.058 56.192,-20.058 ; 55.481,-20.033 56.192,-20.033 ; 55.481,-20.008 56.192,-20.008 ; 55.481,-19.982 56.192,-19.982 ; 55.481,-19.957 56.192,-19.957 ; 55.481,-19.931 56.192,-19.931 ; 55.481,-19.906 56.192,-19.906 ; 55.481,-19.881 56.192,-19.881 ; 55.481,-19.855 56.192,-19.855 ; 55.481,-19.83 56.192,-19.83 ; 55.481,-19.804 56.192,-19.804 ; 55.481,-19.779 56.192,-19.779 ; 55.481,-19.754 56.167,-19.754 ; 55.481,-19.728 55.862,-19.728 ; 55.481,-19.703 55.862,-19.703 ; 55.481,-19.677 55.862,-19.677 ; 55.481,-19.652 55.862,-19.652 ; 55.481,-19.627 55.862,-19.627 ; 55.481,-19.601 55.862,-19.601 ; 55.481,-19.576 55.862,-19.576 ; 55.481,-19.55 55.862,-19.55 ; 55.481,-19.525 55.862,-19.525 ; 55.481,-19.5 55.862,-19.5 ; 55.481,-19.474 55.862,-19.474 ; 55.481,-18.738 55.862,-18.738 ; 55.481,-18.712 55.862,-18.712 ; 55.481,-18.687 55.862,-18.687 ; 55.481,-18.661 55.862,-18.661 ; 55.481,-18.636 55.862,-18.636 ; 55.481,-18.611 55.862,-18.611 ; 55.481,-18.585 55.862,-18.585 ; 55.481,-18.56 55.862,-18.56 ; 55.481,-18.534 55.862,-18.534 ; 55.481,-18.509 55.862,-18.509 ; 55.481,-18.484 55.862,-18.484 ; 55.481,-18.458 55.862,-18.458 ; 55.481,-17.747 55.862,-17.747 ; 55.481,-17.722 55.862,-17.722 ; 55.481,-17.696 55.862,-17.696 ; 55.481,-17.671 55.862,-17.671 ; 55.481,-17.645 55.862,-17.645 ; 55.481,-17.62 55.862,-17.62 ; 55.481,-17.595 55.862,-17.595 ; 55.481,-17.569 55.862,-17.569 ; 55.481,-17.544 55.862,-17.544 ; 55.481,-17.518 55.862,-17.518 ; 55.481,-17.493 55.862,-17.493 ; 55.481,-17.468 55.862,-17.468 ; 55.481,-16.401 55.862,-16.401 ; 55.481,-16.375 55.862,-16.375 ; 55.481,-16.35 55.862,-16.35 ; 55.481,-16.325 55.862,-16.325 ; 55.481,-16.299 55.862,-16.299 ; 55.481,-16.274 55.862,-16.274 ; 55.481,-16.248 55.862,-16.248 ; 55.481,-16.223 55.862,-16.223 ; 55.481,-16.198 55.862,-16.198 ; 55.481,-16.172 55.862,-16.172 ; 55.481,-16.147 55.862,-16.147 ; 55.481,-16.121 55.862,-16.121 ; 55.481,-15.766 55.862,-15.766 ; 55.481,-15.74 55.862,-15.74 ; 55.481,-15.715 55.862,-15.715 ; 55.481,-15.69 55.862,-15.69 ; 55.481,-15.664 55.862,-15.664 ; 55.481,-15.639 55.862,-15.639 ; 55.481,-15.613 55.862,-15.613 ; 55.481,-15.588 55.862,-15.588 ; 55.481,-15.563 55.862,-15.563 ; 55.481,-15.537 55.862,-15.537 ; 55.481,-15.512 55.862,-15.512 ; 55.481,-15.486 55.862,-15.486 ; 55.481,-15.08 55.862,-15.08 ; 55.481,-15.055 55.862,-15.055 ; 55.481,-15.029 55.862,-15.029 ; 55.481,-15.004 55.862,-15.004 ; 55.481,-14.978 55.862,-14.978 ; 55.481,-14.953 55.862,-14.953 ; 55.481,-14.928 55.862,-14.928 ; 55.481,-14.902 55.862,-14.902 ; 55.481,-14.877 55.862,-14.877 ; 55.481,-14.851 55.862,-14.851 ; 55.481,-14.826 55.862,-14.826 ; 55.481,-14.801 55.862,-14.801 ; 55.481,-14.775 55.862,-14.775 ; 55.481,-14.75 55.862,-14.75 ; 55.481,-14.724 55.862,-14.724 ; 55.481,-14.699 55.862,-14.699 ; 55.481,-14.674 55.862,-14.674 ; 55.481,-14.648 55.862,-14.648 ; 55.481,-14.623 55.862,-14.623 ; 55.481,-14.597 55.862,-14.597 ; 55.481,-14.572 55.862,-14.572 ; 55.481,-14.547 55.862,-14.547 ; 55.481,-14.521 55.862,-14.521 ; 55.481,-14.496 55.862,-14.496 ; 55.481,-14.47 56.167,-14.47 ; 55.481,-14.445 56.167,-14.445 ; 55.481,-14.42 56.192,-14.42 ; 55.481,-14.394 56.192,-14.394 ; 55.481,-14.369 56.192,-14.369 ; 55.481,-14.343 56.192,-14.343 ; 55.481,-14.318 56.192,-14.318 ; 55.481,-14.293 56.192,-14.293 ; 55.481,-14.267 56.192,-14.267 ; 55.481,-14.242 56.192,-14.242 ; 55.481,-14.216 56.192,-14.216 ; 55.481,-14.191 56.192,-14.191 ; 55.481,-14.166 56.192,-14.166 ; 55.481,-14.14 56.192,-14.14 ; 55.481,-14.115 56.192,-14.115 ; 55.481,-14.089 56.192,-14.089 ; 55.481,-14.064 56.192,-14.064 ; 55.481,-14.039 56.192,-14.039 ; 55.481,-14.013 56.192,-14.013 ; 55.481,-13.988 56.192,-13.988 ; 55.481,-13.962 56.192,-13.962 ; 55.481,-13.937 56.192,-13.937 ; 55.481,-13.912 56.192,-13.912 ; 55.481,-13.886 56.192,-13.886 ; 55.481,-13.861 56.192,-13.861 ; 55.481,-13.835 56.192,-13.835 ; 55.481,-13.81 56.192,-13.81 ; 55.481,-12.413 55.862,-12.413 ; 55.481,-12.388 55.862,-12.388 ; 55.481,-12.362 55.862,-12.362 ; 55.481,-12.337 55.862,-12.337 ; 55.481,-12.311 55.862,-12.311 ; 55.481,-12.286 55.862,-12.286 ; 55.481,-12.261 55.862,-12.261 ; 55.481,-12.235 55.862,-12.235 ; 55.481,-12.21 55.862,-12.21 ; 55.481,-12.184 55.862,-12.184 ; 55.481,-12.159 55.862,-12.159 ; 55.481,-12.134 55.862,-12.134 ; 55.481,-12.108 55.862,-12.108 ; 55.481,-12.083 55.862,-12.083 ; 55.481,-12.057 55.862,-12.057 ; 55.481,-12.032 55.862,-12.032 ; 55.481,-12.007 55.862,-12.007 ; 55.481,-11.981 55.862,-11.981 ; 55.481,-11.956 55.862,-11.956 ; 55.481,-11.93 55.862,-11.93 ; 55.481,-11.905 55.862,-11.905 ; 55.481,-11.88 55.862,-11.88 ; 55.481,-11.854 55.862,-11.854 ; 55.481,-11.829 55.862,-11.829 ; 55.481,-11.803 56.548,-11.803 ; 55.481,-11.778 56.548,-11.778 ; 55.481,-11.753 56.192,-11.753 ; 55.481,-11.727 56.192,-11.727 ; 55.481,-11.702 56.192,-11.702 ; 55.481,-11.676 56.192,-11.676 ; 55.481,-11.651 56.192,-11.651 ; 55.481,-11.626 56.192,-11.626 ; 55.481,-11.6 56.192,-11.6 ; 55.481,-11.575 56.192,-11.575 ; 55.481,-11.549 56.192,-11.549 ; 55.481,-11.524 56.192,-11.524 ; 55.481,-11.499 56.192,-11.499 ; 55.481,-11.473 56.192,-11.473 ; 55.481,-11.118 56.852,-11.118 ; 55.481,-11.092 56.852,-11.092 ; 55.481,-11.067 56.852,-11.067 ; 55.481,-11.041 56.852,-11.041 ; 55.481,-11.016 56.852,-11.016 ; 55.481,-10.991 56.852,-10.991 ; 55.481,-10.965 56.852,-10.965 ; 55.481,-10.94 56.852,-10.94 ; 55.481,-10.914 56.852,-10.914 ; 55.481,-10.889 56.852,-10.889 ; 55.481,-10.864 56.852,-10.864 ; 55.481,-10.838 56.852,-10.838 ; 55.481,-10.813 56.852,-10.813 ; 55.481,-10.787 56.852,-10.787 ; 55.481,-10.762 56.192,-10.762 ; 55.481,-10.737 56.192,-10.737 ; 55.481,-10.711 56.192,-10.711 ; 55.481,-10.686 56.192,-10.686 ; 55.481,-10.66 56.192,-10.66 ; 55.481,-10.635 56.192,-10.635 ; 55.481,-10.61 56.192,-10.61 ; 55.481,-10.584 56.192,-10.584 ; 55.481,-10.559 56.192,-10.559 ; 55.481,-10.533 56.192,-10.533 ; 55.481,-10.508 56.192,-10.508 ; 55.481,-10.483 56.192,-10.483 ; 55.481,-10.457 56.548,-10.457 ; 55.481,-10.432 56.548,-10.432 ; 55.481,-10.406 56.548,-10.406 ; 55.481,-10.381 56.548,-10.381 ; 55.481,-10.356 56.548,-10.356 ; 55.481,-10.33 56.548,-10.33 ; 55.481,-10.305 56.548,-10.305 ; 55.481,-10.279 56.548,-10.279 ; 55.481,-10.254 56.548,-10.254 ; 55.481,-10.229 56.548,-10.229 ; 55.481,-10.203 56.548,-10.203 ; 55.481,-10.178 56.548,-10.178 ; 55.481,-10.152 56.548,-10.152 ; 55.506,-17.442 55.862,-17.442 ; 55.506,-17.417 55.862,-17.417 ; 55.506,-11.448 56.548,-11.448 ; 55.506,-10.127 56.548,-10.127 ; 55.506,-10.102 56.548,-10.102 ; 55.811,-18.077 56.192,-18.077 ; 55.811,-18.052 56.192,-18.052 ; 55.811,-18.026 56.192,-18.026 ; 55.811,-18.001 56.192,-18.001 ; 55.811,-17.976 56.192,-17.976 ; 55.811,-17.95 56.192,-17.95 ; 55.811,-17.925 56.192,-17.925 ; 55.811,-17.899 56.192,-17.899 ; 55.811,-17.874 56.192,-17.874 ; 55.811,-17.849 56.192,-17.849 ; 55.811,-17.823 56.192,-17.823 ; 55.811,-17.798 56.192,-17.798 ; 55.811,-13.734 57.843,-13.734 ; 55.811,-13.708 57.843,-13.708 ; 55.811,-13.683 57.843,-13.683 ; 55.811,-13.658 57.843,-13.658 ; 55.811,-13.632 57.843,-13.632 ; 55.811,-13.607 57.843,-13.607 ; 55.811,-13.581 57.843,-13.581 ; 55.811,-13.556 57.843,-13.556 ; 55.811,-13.531 57.843,-13.531 ; 55.811,-13.505 57.843,-13.505 ; 55.811,-13.48 57.843,-13.48 ; 55.811,-13.454 57.843,-13.454 ; 55.811,-12.794 59.164,-12.794 ; 55.811,-12.769 59.164,-12.769 ; 55.811,-12.743 56.192,-12.743 ; 55.811,-12.718 56.192,-12.718 ; 55.811,-12.692 56.192,-12.692 ; 55.811,-12.667 56.192,-12.667 ; 55.811,-12.642 56.192,-12.642 ; 55.811,-12.616 56.192,-12.616 ; 55.811,-12.591 56.192,-12.591 ; 55.811,-12.565 56.192,-12.565 ; 55.811,-12.54 56.192,-12.54 ; 55.811,-12.515 56.192,-12.515 ; 55.811,-12.489 56.192,-12.489 ; 55.811,-12.464 56.192,-12.464 ; 55.811,-11.422 56.548,-11.422 ; 55.811,-11.397 56.548,-11.397 ; 55.811,-11.372 56.548,-11.372 ; 55.811,-11.346 56.548,-11.346 ; 55.811,-11.321 56.548,-11.321 ; 55.811,-11.295 56.548,-11.295 ; 55.811,-11.27 56.548,-11.27 ; 55.811,-11.245 56.548,-11.245 ; 55.811,-11.219 56.548,-11.219 ; 55.811,-11.194 56.548,-11.194 ; 55.811,-11.168 56.548,-11.168 ; 55.811,-11.143 56.548,-11.143 ; 55.811,-10.076 56.548,-10.076 ; 55.811,-10.051 56.548,-10.051 ; 55.811,-10.025 56.548,-10.025 ; 55.811,-10 56.548,-10 ; 55.811,-9.975 56.548,-9.975 ; 55.811,-9.949 56.548,-9.949 ; 55.811,-9.924 56.548,-9.924 ; 55.811,-9.898 56.548,-9.898 ; 55.811,-9.873 56.548,-9.873 ; 55.811,-9.848 56.548,-9.848 ; 55.811,-9.822 56.548,-9.822 ; 55.811,-9.797 56.548,-9.797 ; 55.862,-18.128 55.887,-18.128 ; 55.862,-18.103 55.887,-18.103 ; 56.04,-18.128 56.167,-18.128 ; 56.04,-18.103 56.167,-18.103 ; 56.167,-20.744 57.183,-20.744 ; 56.167,-20.719 57.183,-20.719 ; 56.167,-20.693 57.183,-20.693 ; 56.167,-20.668 57.183,-20.668 ; 56.167,-20.643 57.183,-20.643 ; 56.167,-20.617 57.183,-20.617 ; 56.167,-20.592 57.183,-20.592 ; 56.167,-20.566 57.183,-20.566 ; 56.167,-20.541 57.183,-20.541 ; 56.167,-20.516 57.183,-20.516 ; 56.167,-20.49 57.183,-20.49 ; 56.167,-20.465 57.183,-20.465 ; 56.167,-17.747 56.852,-17.747 ; 56.167,-17.722 56.852,-17.722 ; 56.167,-17.696 56.852,-17.696 ; 56.167,-17.671 56.852,-17.671 ; 56.167,-17.645 56.852,-17.645 ; 56.167,-17.62 56.852,-17.62 ; 56.167,-17.595 56.852,-17.595 ; 56.167,-17.569 56.852,-17.569 ; 56.167,-17.544 56.852,-17.544 ; 56.167,-17.518 56.852,-17.518 ; 56.167,-17.493 56.852,-17.493 ; 56.167,-17.468 56.852,-17.468 ; 56.167,-17.442 57.538,-17.442 ; 56.167,-17.417 57.538,-17.417 ; 56.167,-17.391 57.183,-17.391 ; 56.167,-17.366 57.183,-17.366 ; 56.167,-17.341 57.183,-17.341 ; 56.167,-17.315 57.183,-17.315 ; 56.167,-17.29 57.183,-17.29 ; 56.167,-17.264 57.183,-17.264 ; 56.167,-17.239 57.183,-17.239 ; 56.167,-17.214 57.183,-17.214 ; 56.167,-17.188 57.183,-17.188 ; 56.167,-17.163 57.183,-17.163 ; 56.167,-17.137 57.183,-17.137 ; 56.167,-17.112 57.183,-17.112 ; 56.167,-15.105 57.386,-15.105 ; 56.167,-15.08 56.852,-15.08 ; 56.167,-15.055 56.852,-15.055 ; 56.167,-15.029 56.852,-15.029 ; 56.167,-15.004 56.852,-15.004 ; 56.167,-14.978 56.852,-14.978 ; 56.167,-14.953 56.852,-14.953 ; 56.167,-14.928 56.852,-14.928 ; 56.167,-14.902 56.852,-14.902 ; 56.167,-14.877 56.852,-14.877 ; 56.167,-14.851 56.852,-14.851 ; 56.167,-14.826 56.852,-14.826 ; 56.167,-14.801 56.852,-14.801 ; 56.167,-13.124 58.834,-13.124 ; 56.167,-13.099 57.538,-13.099 ; 56.167,-13.073 57.538,-13.073 ; 56.167,-13.048 57.538,-13.048 ; 56.167,-13.023 57.538,-13.023 ; 56.167,-12.997 57.538,-12.997 ; 56.167,-12.972 57.538,-12.972 ; 56.167,-12.946 57.538,-12.946 ; 56.167,-12.921 57.538,-12.921 ; 56.167,-12.896 57.538,-12.896 ; 56.167,-12.87 57.538,-12.87 ; 56.167,-12.845 57.538,-12.845 ; 56.167,-12.819 57.538,-12.819 ; 56.167,-12.413 57.538,-12.413 ; 56.167,-12.388 57.538,-12.388 ; 56.167,-12.362 57.538,-12.362 ; 56.167,-12.337 57.538,-12.337 ; 56.167,-12.311 57.538,-12.311 ; 56.167,-12.286 57.538,-12.286 ; 56.167,-12.261 57.538,-12.261 ; 56.167,-12.235 57.538,-12.235 ; 56.167,-12.21 57.538,-12.21 ; 56.167,-12.184 57.538,-12.184 ; 56.167,-12.159 57.538,-12.159 ; 56.167,-12.134 57.843,-12.134 ; 56.167,-12.108 56.548,-12.108 ; 56.167,-12.083 56.548,-12.083 ; 56.167,-12.057 56.548,-12.057 ; 56.167,-12.032 56.548,-12.032 ; 56.167,-12.007 56.548,-12.007 ; 56.167,-11.981 56.548,-11.981 ; 56.167,-11.956 56.548,-11.956 ; 56.167,-11.93 56.548,-11.93 ; 56.167,-11.905 56.548,-11.905 ; 56.167,-11.88 56.548,-11.88 ; 56.167,-11.854 56.548,-11.854 ; 56.167,-11.829 56.548,-11.829 ; 56.497,-22.09 56.852,-22.09 ; 56.497,-22.065 56.852,-22.065 ; 56.497,-22.04 56.852,-22.04 ; 56.497,-22.014 56.852,-22.014 ; 56.497,-21.989 56.852,-21.989 ; 56.497,-21.963 56.852,-21.963 ; 56.497,-21.938 56.852,-21.938 ; 56.497,-21.913 56.852,-21.913 ; 56.497,-21.887 56.852,-21.887 ; 56.497,-21.862 56.852,-21.862 ; 56.497,-21.836 56.852,-21.836 ; 56.497,-21.811 56.852,-21.811 ; 56.497,-21.1 57.843,-21.1 ; 56.497,-21.074 57.843,-21.074 ; 56.497,-21.049 56.852,-21.049 ; 56.497,-21.024 56.852,-21.024 ; 56.497,-20.998 56.852,-20.998 ; 56.497,-20.973 56.852,-20.973 ; 56.497,-20.947 56.852,-20.947 ; 56.497,-20.922 56.852,-20.922 ; 56.497,-20.897 56.852,-20.897 ; 56.497,-20.871 56.852,-20.871 ; 56.497,-20.846 56.852,-20.846 ; 56.497,-20.82 56.852,-20.82 ; 56.497,-20.795 56.852,-20.795 ; 56.497,-20.77 56.852,-20.77 ; 56.497,-19.449 59.824,-19.449 ; 56.497,-19.423 57.538,-19.423 ; 56.497,-19.398 57.538,-19.398 ; 56.497,-19.373 57.538,-19.373 ; 56.497,-19.347 57.538,-19.347 ; 56.497,-19.322 57.538,-19.322 ; 56.497,-19.296 57.538,-19.296 ; 56.497,-19.271 57.538,-19.271 ; 56.497,-19.246 57.538,-19.246 ; 56.497,-19.22 57.538,-19.22 ; 56.497,-19.195 57.538,-19.195 ; 56.497,-19.169 57.538,-19.169 ; 56.497,-19.144 57.538,-19.144 ; 56.497,-18.433 58.173,-18.433 ; 56.497,-18.407 58.173,-18.407 ; 56.497,-18.382 58.173,-18.382 ; 56.497,-18.357 58.173,-18.357 ; 56.497,-18.331 58.173,-18.331 ; 56.497,-18.306 58.173,-18.306 ; 56.497,-18.28 58.173,-18.28 ; 56.497,-18.255 58.173,-18.255 ; 56.497,-18.23 58.173,-18.23 ; 56.497,-18.204 58.173,-18.204 ; 56.497,-18.179 58.173,-18.179 ; 56.497,-18.153 58.173,-18.153 ; 56.497,-18.128 58.173,-18.128 ; 56.497,-18.103 58.173,-18.103 ; 56.497,-18.077 57.843,-18.077 ; 56.497,-18.052 57.843,-18.052 ; 56.497,-18.026 57.843,-18.026 ; 56.497,-18.001 57.843,-18.001 ; 56.497,-17.976 57.843,-17.976 ; 56.497,-17.95 57.843,-17.95 ; 56.497,-17.925 57.843,-17.925 ; 56.497,-17.899 57.843,-17.899 ; 56.497,-17.874 57.843,-17.874 ; 56.497,-17.849 57.843,-17.849 ; 56.497,-17.823 57.843,-17.823 ; 56.497,-17.798 57.843,-17.798 ; 56.497,-17.087 57.183,-17.087 ; 56.497,-17.061 57.183,-17.061 ; 56.497,-17.036 57.183,-17.036 ; 56.497,-17.01 57.183,-17.01 ; 56.497,-16.985 57.183,-16.985 ; 56.497,-16.96 57.183,-16.96 ; 56.497,-16.934 57.183,-16.934 ; 56.497,-16.909 57.183,-16.909 ; 56.497,-16.883 57.183,-16.883 ; 56.497,-16.858 57.183,-16.858 ; 56.497,-16.833 57.183,-16.833 ; 56.497,-16.807 57.183,-16.807 ; 56.497,-16.782 57.386,-16.782 ; 56.497,-16.452 57.386,-16.452 ; 56.497,-16.426 57.386,-16.426 ; 56.497,-16.401 57.386,-16.401 ; 56.497,-16.375 57.386,-16.375 ; 56.497,-16.35 57.386,-16.35 ; 56.497,-16.325 57.386,-16.325 ; 56.497,-16.299 57.386,-16.299 ; 56.497,-16.274 57.386,-16.274 ; 56.497,-16.248 57.386,-16.248 ; 56.497,-16.223 57.386,-16.223 ; 56.497,-16.198 57.386,-16.198 ; 56.497,-16.172 57.386,-16.172 ; 56.497,-16.147 57.386,-16.147 ; 56.497,-16.121 57.386,-16.121 ; 56.497,-15.766 57.386,-15.766 ; 56.497,-15.74 57.386,-15.74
